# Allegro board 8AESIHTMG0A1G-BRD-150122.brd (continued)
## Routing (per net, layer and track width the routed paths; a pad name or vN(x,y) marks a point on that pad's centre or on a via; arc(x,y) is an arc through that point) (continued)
VCC3P3: length 210.4
  TOP w0.305: 48.98,67.35 C53.1 48.96,68.05 R57.1 ; 48.98,67.35 v4(49.73,66.6) ; 48.98,67.35 48.98,67.14 v4(48.56,66.73) ; v1(42.29,93.22) 42.19,93.22 42.12,93.15 U4.7
  TOP w0.356: v1(36.69,92.79) 36.66,92.82 U8.1
  TOP w0.635: U9.2 v3(47.47,87.66) ; U5.2 v3(29.18,91.89)
  TOP w0.762: 27.79,89.84 27.79,89.05 v4(27.64,88.9) ; 27.79,89.84 27.23,89.28 v4(26.54,89.28) ; 27.79,89.84 U5.1 ; 46.28,89.93 U9.1 ; 46.28,89.93 46.4,89.93 47.13,90.65 v4(47.14,90.65) ; 46.28,89.93 46.28,90.2 v4(45.87,90.61)
  L3_VCC w0.508: 34.37,169.7 34.37,170.18 v6(34.34,170.21)
  L3_VCC w1.524: v3(32.82,170.1) 33.96,170.1 38.5,165.57 41.39,165.57 42.41,164.55 ; 42.41,164.55 41.95,164.55 v4(41.31,163.92) ; 42.41,164.55 v4(43.07,163.89)
  BOTTOM w0.203: v1(47.42,66.65) 55.85,58.22 55.85,7.29 53.81,5.25 51.67,5.25 P2.24
  BOTTOM w0.305: v1(39.59,90.96) 39.61,90.98 R83.2 ; R82.2 42.27,91.76 v1(42.08,91.57) ; C82.1 42.12,93.15 42.19,93.22 v1(42.29,93.22)
  BOTTOM w0.356: v1(36.69,92.79) C84.1
  BOTTOM w0.508: J10.A21 33.4,169.52 v3(32.82,170.1) ; C87.1 29.21,91.87 v3(29.18,91.89) ; v6(34.34,170.21) 34.34,170.17 34.2,170.04 J10.A22 ; C89.1 47.34,87.53 v3(47.47,87.66)
  BOTTOM w0.635: v4(47.14,90.65) 47.1,90.61 46.97,90.61 46.57,90.22 46.57,90.06 ; 27.56,89.5 C85.1 ; 27.56,89.5 27.39,89.33 26.62,89.33 26.57,89.28 v4(26.54,89.28) ; 27.56,89.5 27.56,88.92 27.58,88.9 v4(27.64,88.9) ; 46.57,90.06 C88.1 ; 46.57,90.06 46.02,90.61 v4(45.87,90.61)
  BOTTOM w1.524: v4(51.08,82.3) 52.86,82.3 ; 52.86,82.3 v4(50.81,80.26) ; 52.86,82.3 55.22,84.66 55.22,105.36 52.3,108.28 52.3,111.66 54.69,114.05 54.69,148.93 43.07,160.55 43.07,162.67 ; 43.07,162.67 v4(43.07,163.89) ; 43.07,162.67 41.82,163.92 v4(41.31,163.92)
VDD1P2: length 30.4
  TOP w0.254: U10.47 38.22,83.54 v3(38.02,83.74) ; U10.43 38.17,81.54 v3(37.9,81.81) ; v3(37.85,79.15) 37.95,79.15 38.35,79.54 U10.39 ; v3(31.83,85.89) 31.83,85.72 31.88,85.67 U10.62 ; v3(30.35,86.09) 30.88,85.55 U10.64
  TOP w0.356: v1(26.82,78.87) 27.06,78.63 N4.2 ; N3.2 v1(26.92,85.12)
  TOP w0.508: R8.1 33.08,92.89 30.95,92.89 30.45,92.38 30.45,90.55 U5.3
  TOP w0.762: v3(30.2,88.85) 30.45,89.1 30.45,89.63 ; v4(31.22,89.05) 31.03,89.05 30.45,89.63 ; 30.45,89.63 U5.3
  BOTTOM w0.305: C91.1 40.29,84 v3(40.41,83.88) ; C97.1 30.81,83.78 31.2,83.39 v3(31.24,83.39) ; C102.1 30.82,81.4 31.13,81.71 v3(31.14,81.71)
  BOTTOM w0.356: v3(37.85,79.15) 37.92,79.15 38.42,79.64 C104.1 ; C94.1 32.25,85.47 v3(31.83,85.89) ; C96.1 38.19,83.58 v3(38.02,83.74) ; C95.1 30.59,85.84 v3(30.35,86.09) ; v3(37.9,81.81) 38.16,81.55 C101.1
  BOTTOM w0.508: v3(28.75,86.84) 28.38,86.46 C90.1
  BOTTOM w0.635: v3(30.2,88.85) 30.27,88.85 30.5,89.07 30.5,89.58 ; 30.5,89.58 C86.1 ; 30.5,89.58 31.03,89.05 v4(31.22,89.05)
VDD2P5: length 54.1
  TOP w0.254: v1(45.44,93.7) 45.39,93.65 U4.3 ; U10.37 39.96,78.54 v3(40.43,78.07) ; v3(35.23,86) 35.22,86 34.88,85.67 U10.56
  TOP w0.305: C56.1 28.1,63.75 v1(28.35,63.99) ; v1(29.82,63.14) 29.84,63.14 29.88,63.11 C57.2 ; C21.2 v1(50.87,90.68) ; C55.2 v1(51.77,65.04)
  TOP w0.356: T1.10 36.53,64.26 v1(36.2,64.59) ; T1.1 48.09,64.11 v1(47.57,64.62) ; R7.2 38.53,93.64 v1(38.48,93.6) ; v1(31.67,87.3) 31.68,87.29 R20.2 ; v1(38.86,92.84) 38.84,92.82 U8.6 ; R23.1 45.13,84.81 v1(45.16,84.84) ; v1(47.17,93.45) 47.15,93.43 R6.1 ; v1(44.12,64.54) 44.12,63.09 T1.4 ; R5.1 v1(38.5,94.66) ; R13.1 v1(38.23,89.13) ; R17.1 v1(42.32,89.05) ; v1(44.27,81.33) 44.2,81.4 R31.1 ; T1.7 v1(40.34,64.57) ; R10.1 v1(32.85,88.87) ; R36.1 43.28,78.19 v1(43.59,77.88) ; R16.1 v1(41.27,89.05) ; R11.2 v1(35.18,89)
  TOP w0.508: R29.1 45.09,81.8 v3(45.07,81.82)
  TOP w0.762: 44.8,86.39 44.8,86.03 v3(44.4,85.64) ; 44.8,86.39 v3(44.8,86.54) ; 44.8,86.39 U9.3
  BOTTOM w0.305: C80.1 21.7,93.6 v1(22.09,93.21) ; v1(22.83,77.75) 22.29,77.2 C107.1 ; v1(45.44,93.7) 45.37,93.77 C81.1 ; C76.2 v1(26.72,96.12) ; C75.2 v1(51.96,95.68)
  BOTTOM w0.356: 25.7,84.17 25.76,84.11 C98.1 ; v3(40.43,78.07) 40.03,78.47 C106.1 ; v1(36.2,64.59) 36.53,64.26 C128.1 ; C83.1 38.82,92.8 v1(38.86,92.84) ; 26.54,74.5 26.56,74.51 C120.1 ; C126.1 v1(44.12,64.54) ; C93.1 34.81,85.6 35.22,86 v3(35.23,86) ; C117.1 44.42,75.01 44.47,74.96 ; v1(47.57,64.62) 48.08,64.11 C129.1 ; C127.1 40.34,63.77 v1(40.34,64.57)
  BOTTOM w0.508: 26.54,74.02 25.82,73.3 v4(25.68,73.3) ; 26.54,74.02 26.54,73.54 26.54,72.62 v4(26.54,72.62) ; 26.54,74.02 L8.1 ; v4(44.97,73.65) 44.97,73.76 44.47,74.25 ; 45.12,86.21 C92.1 ; 45.12,86.21 44.98,86.21 v3(44.4,85.64) ; 45.12,86.21 v3(44.8,86.54) ; v4(43.86,73.68) 43.9,73.68 44.47,74.25 ; 25.7,84.17 24.77,84.17 v4(24.77,84.17) ; 25.7,84.17 25.7,84.92 v4(25.6,85.02) ; 25.7,84.17 L7.1 ; 44.47,74.25 44.47,74.96 43.25,74.96 L9.1
VDD5P0SB: length 20.5
  TOP w0.762: F1.2 9.88,170.79 10.58,170.1 v7(10.62,170.1)
  BOTTOM w0.254: 10.52,170.07 R81.1
  BOTTOM w0.635: J10.A5 20.6,166.52 20.19,166.1 19.79,166.1 19.8,166.11 J10.A4
  BOTTOM w0.762: v7(10.62,170.1) 10.55,170.1 10.52,170.07 10.52,166.43 11.42,165.53 15.24,165.53 15.81,166.1 19.79,166.1
VDD12P0: length 81.4
  TOP w0.305: 25.21,99.23 C17.1 25.73,99.72
  TOP w0.508: U2.3 27.38,101.6 ; U2.3 27.38,100.23 ; U2.3 28.32,100.91 ; U2.3 26.44,100.91 ; 25.77,101.02 C16.1 25.34,100.37
  TOP w0.762: v4(22.63,143.7) 19.81,146.52 19.81,168.59 20.88,169.66 v7(20.88,169.96)
  BOTTOM w0.635: J10.A6 21.4,169.43 20.88,169.94 v7(20.88,169.96)
  BOTTOM w0.762: v4(25.82,99.1) 25.82,112.48 22.63,115.66 v4(22.63,143.7)
1PPS_OUT_CLK: length 174.1
  TOP w0.203: P4.1 7,12.08 8.35,13.43 D4.1 9.09,14.4 9.74,15.05 9.74,19.19 2.08,26.85 2.08,95.19 12.48,105.59 v1(12.48,167.12)
  BOTTOM w0.203: J10.A1 15.3,167.89 14.48,167.08 12.52,167.08 v1(12.48,167.12)
88E1112_25M_REFCLK: length 102.4
  TOP w0.203: v1(44.45,78.99) 44.46,78.98 R38.2 44.46,78.1 R39.1
  BOTTOM w0.203: v1(44.45,78.99) 44.45,79.69 49.65,84.89 49.65,97.48 53.27,101.09 53.27,103.92 50.29,106.9 50.29,112.51 51.94,114.16 51.94,148.87 37.4,163.42 J10.A26
88E1112_INT_L: length 102.2
  TOP w0.203: U8.3 36.39,91.37 v1(36.7,91.06) ; v1(35.26,157.02) 37.4,159.17 v1(37.4,170.78)
  BOTTOM w0.203: J10.B26 v1(37.4,170.78) ; v1(35.26,157.02) 34.67,157.02 28.06,150.41 25.53,150.41 20.29,145.17 20.29,100.51 26.6,94.19 31.79,94.19 34.92,91.06 v1(36.7,91.06)
88E1112_RST_L: length 102.6
  TOP w0.203: C22.1 36.19,87.64 36.19,86.54 v1(36.45,86.28) 36.88,85.85 U10.52
  BOTTOM w0.203: J10.A24 35.8,158.89 27.74,150.83 25.31,150.83 19.87,145.39 19.87,100.33 26.44,93.76 31.47,93.76 34.46,90.76 34.46,88.86 36.45,86.87 v1(36.45,86.28)
5221_50M_RMII_REFCLK: length 106.4
  TOP w0.203: v1(23.65,165.07) 23.65,164.54 v5(21.99,162.88) ; v1(8.15,74.9) 8.34,74.72 9.4,74.72 9.57,74.89 U11.4
  BOTTOM w0.203: v1(8.15,74.9) 8.15,77.22 11.53,80.59 11.53,155.77 18.48,162.73 21.84,162.73 v5(21.99,162.88) ; J10.A13 27,166.45 25.62,165.07 v1(23.65,165.07)
5221_ACTLED: length 5.7
  TOP w0.203: U12.2 24.15,66.17 24.03,66.3 R62.2 R61.1 22.42,66.58 22.07,66.93 v1(22.07,67.56) U11.33
5221_AVDD: length 11.3
  TOP w0.254: v3(14.71,65.56) 15.01,65.86 U11.22 ; v3(17.5,65.51) 17.51,65.51 U11.27 ; v3(18.41,65.52) 18.41,65.53 18.01,65.94 U11.28
  BOTTOM w0.356: v3(17.5,65.51) 17.5,65.62 17.28,65.84 C122.1 ; C124.1 18.3,65.65 18.33,65.61 ; C123.1 15.07,65.92 v3(14.71,65.56)
  BOTTOM w0.508: v3(14.71,65.56) 17.45,65.56 v3(17.5,65.51) 17.61,65.61 18.33,65.61 18.41,65.53 v3(18.41,65.52)
5221_INT_L: length 111.6
  TOP w0.203: v1(25.98,153.09) 26.37,153.47 26.37,170.84 v1(26.2,171.01) ; v1(23.39,68.76) 23.39,68.97 22.97,69.39 U11.34
  BOTTOM w0.203: J10.B12 v1(26.2,171.01) ; v1(23.39,68.76) 23.39,73.17 24.37,74.15 24.37,80.53 22.95,81.96 22.95,88.96 23.49,89.5 23.49,95.54 19.03,100 19.03,145.86 25.96,152.78 25.96,153.06 v1(25.98,153.09)
5221_LNKACT: length 29.4
  TOP w0.203: v1(26.46,65.43) 26.49,65.45 U12.4 ; v1(24.18,88.78) 22.97,88.78 22.76,88.98 U6.5
  BOTTOM w0.203: v1(26.46,65.43) 25.81,66.08 25.81,68.26 24.39,69.68 24.39,72.94 25.49,74.03 25.49,80.78 23.84,82.42 23.84,88.44 v1(24.18,88.78)
5221_LNKACT_B: length 102.6
  TOP w0.203: U6.10 22.76,97.33 23.33,97.9 33.58,97.9 v2(34.19,97.29) 34.83,96.65 52.81,96.65 55.88,93.57 55.88,33.07 52.37,29.57 R78.1
5221_LNKACT_C: length 86.7
  TOP w0.203: v1(34.09,165.4) 34.78,164.71 34.78,159.86 29.78,154.86 v1(29.78,154.28) ; U6.8 25.43,95.09 v1(24.83,94.49)
  BOTTOM w0.203: J10.A19 31.8,166.5 32.9,165.4 v1(34.09,165.4) ; v1(24.83,94.49) 24.83,94.78 19.44,100.17 19.44,145.61 25.1,151.27 26.77,151.27 v1(29.78,154.28)
5221_RD_N: length 14.7
  TOP w0.152: 16.42,64.52 16.58,64.68 16.58,65.82 16.51,65.89 U11.25 ; 16.42,64.52 R65.1 ; 16.42,64.52 16.58,64.36 16.58,62.42 18.82,60.17 21.85,60.17 22.02,60.01 22.02,59.61 21.84,59.44 21.21,59.44 20.76,58.99 T2.8
5221_RD_P: length 14.4
  TOP w0.152: 17.02,64.5 16.93,64.41 16.93,62.56 18.97,60.53 22,60.53 22.37,60.15 22.37,59.54 22.48,59.44 22.86,59.44 23.43,58.87 T2.6 ; 17.02,64.5 R68.1 ; 17.02,64.5 16.93,64.59 16.93,65.82 17.01,65.89 U11.26
5221_RST_L: length 113.6
  TOP w0.203: v1(12.62,72.75) 12.27,72.39 U11.9 ; v1(22.71,166.28) 22.28,165.85 22.28,164.8 v1(21.82,164.34)
  BOTTOM w0.203: J10.A11 25.4,166.51 25.17,166.28 v1(22.71,166.28) ; v1(21.82,164.34) 21.81,164.34 21.32,163.84 17.91,163.84 10.43,156.37 10.43,81.67 7.24,78.48 7.24,73.59 7.95,72.87 8.6,72.87 9.06,72.42 12.29,72.42 v1(12.62,72.75)
5221_SPDLED: length 68
  TOP w0.203: v1(35.89,27.25) 35.96,27.18 R79.1 ; R55.2 25.37,70.38 25.73,70.03 25.73,67.2 U12.1 v1(24.52,66.9) 24.17,67.24 R59.2
  BOTTOM w0.203: v1(35.89,27.25) 34.7,28.44 32.37,28.44 30.76,30.05 30.76,35.89 24.64,42.01 18.86,42.01 14.5,46.36 14.5,58.32 18.08,61.9 23.37,61.9 25.02,63.55 25.02,66.4 v1(24.52,66.9)
5221_TD_N: length 18.6
  TOP w0.152: 19.18,64.51 19.3,64.64 19.3,65.02 19.08,65.25 19.08,65.82 19.01,65.89 U11.30 ; 19.18,64.51 19.3,64.39 19.3,62.64 20.09,61.85 27.33,61.85 28.32,60.86 28.32,59.56 28.19,59.44 27.69,59.44 27.24,58.99 T2.3 ; 19.18,64.51 R67.1
5221_TD_P: length 18.6
  TOP w0.152: 19.77,64.52 19.66,64.63 19.66,65.17 19.43,65.4 19.43,65.82 19.51,65.89 U11.31 ; 19.77,64.52 19.66,64.41 19.66,62.78 20.24,62.2 27.48,62.2 28.68,61.01 28.68,59.61 28.83,59.46 29.31,59.46 29.91,58.87 T2.1 ; 19.77,64.52 R66.1
ANEN_5221: length 3.7
  TOP w0.203: v1(20.5,71.48) 20.58,71.39 U11.38 24.16,71.39 R54.1
BIAS3V3: length 61.1
  TOP w0.254: U11.8 11.54,72.89 v3(11.7,73.05) ; U11.46 20.85,75.39 v3(20.62,75.62) ; v3(11.66,76.66) 11.5,76.5 U11.1 ; U11.20 14.01,65.9 13.74,65.63 v3(13.59,65.63) ; U11.3 v3(11.69,75.39)
  TOP w0.305: 50.29,26.44 50.24,26.44 49.91,26.11 v3(49.91,25.76) ; 50.29,26.44 49.91,26.82 v3(49.91,27.03) ; 50.29,26.44 C74.1 ; C56.2 v1(26.15,63.75) ; C24.2 v1(6.21,83.54) ; v1(23.57,161.71) 23.29,161.43 C4.2 ; C58.2 v1(7.02,61.33) ; C1.2 v1(10.24,174.82) ; C72.2 v1(12.69,26.98) ; C6.2 v1(6.15,147.15) ; C12.2 v1(6.82,113.01)
  TOP w0.356: R56.1 v1(24.85,68.49) ; R70.2 v1(9.27,59.56) ; P2.20 50.32,24.69 50.78,25.16 C74.1 ; R54.2 v1(25.55,71.4) ; U13.26 7.62,54.73 v1(7.37,54.48) ; R71.2 v1(10.29,59.56) ; R62.1 v1(23.46,64.84) ; R59.1 v1(22.83,68.07) ; R45.2 v1(24.9,72.16)
  TOP w0.381: J9.1 5.64,69.21 4.88,68.45 v1(4.62,68.45) ; J6.1 4.98,72.31 v1(4.6,72.69) ; J5.1 5.69,73.41 4.72,74.37 v1(4.6,74.37) ; J7.1 4.92,71.28 v1(4.6,71.6) ; v1(4.6,70.56) 4.92,70.24 J8.1
  TOP w0.508: v1(26.54,66.93) 26.58,66.9 U12.5 ; J4.3 9.17,88.37 v1(8.64,88.9) ; v1(6.6,94.36) 6.55,94.41 U7.8 ; U6.14 17.55,97.81 v1(17.42,97.94) ; v1(7.77,88.09) 7.9,87.96 J3.3 ; v1(16.1,57.91) 16.1,58.13 L2.1 ; J2.3 v1(6.38,88.09)
  L3_VCC w0.508: 38.2,23.36 P2.18 ; P2.18 39.14,24.3 ; P2.18 40.08,23.36 ; P2.18 39.14,22.42
  BOTTOM w0.305: C107.2 20.57,77.2 v1(20.35,76.98) ; C80.2 v1(20.24,94.01)
  BOTTOM w0.356: C108.2 11.62,76.62 v3(11.66,76.66) ; C79.1 C77.1 17.67,97.7 v1(17.42,97.94) ; v1(6.6,94.36) 6.87,94.63 C78.2 ; v3(11.69,75.39) 11.65,75.43 C118.2 ; v3(20.62,75.62) 20.74,75.5 C119.2 ; v1(7.37,54.48) 7.51,54.62 C132.2 ; C121.2 11.58,72.94 v3(11.7,73.05) ; C125.2 13.95,65.99 v3(13.59,65.63)
  BOTTOM w0.508: J10.B22 34.2,173.9 v3(34.39,174.09) ; v6(33.28,174.22) 33.4,174.1 J10.B21
C1P: length 2.4
  TOP w0.203: C60.2 5.84,57.35 v1(5.79,57.3) 6.19,56.9 U13.28
C2N: length 2.2
  TOP w0.203: U13.2 6.97,47.38 6.81,47.22 v1(6.81,47.22) 6.81,47.07 6.85,47.03 C64.1
C2P: length 2.9
  TOP w0.203: U13.1 6.19,47.12 6.11,47.04 C64.2 v1(5.44,46.35)
CLK_25M_MNGPHY: length 6.2
  TOP w0.203: R39.2 43.71,77.08 R41.2 42.52,77.23 R42.1 40.5,77.23 39.69,78.04 U10.36 38.19,78.04 v1(37.97,78.26)
CLK_25M_OCXO: length 50.4
  TOP w0.203: J1.2 25.43,129.9 24.92,130.4 24.92,164.37 25.19,164.65 25.19,170.36 v5(24.6,170.95)
  BOTTOM w0.203: J10.B10 v5(24.6,170.95)
CPU_PHY_SGMII_N: length 143.5
  TOP w0.152: v1(43.81,176.68) 43.48,176.35 43.48,175.7 43.12,175.34 42.41,175.34 41.84,175.92 24.85,175.92 21.86,172.93 17.27,172.93 16.36,172.01 16.36,101.32 13.11,98.07 13.11,88.23 15.79,85.55 20.7,85.55 25.81,80.44 26.27,80.44 26.6,80.77 C28.1
  BOTTOM w0.152: J10.A30 40.6,169.07 40.42,169.25 40.42,169.47 40.63,169.68 40.89,169.68 41.05,169.84 41.05,170 41.05,170.1 41.2,170.25 41.46,170.25 41.62,170.41 41.62,170.58 41.62,170.67 41.78,170.83 42.04,170.83 42.2,170.99 42.2,171.15 42.2,171.25 42.35,171.4 42.61,171.4 42.77,171.56 42.77,171.73 42.77,171.82 43.48,172.54 43.48,176.35 v1(43.81,176.68)
CPU_PHY_SGMII_P: length 143.5
  TOP w0.152: C29.1 26.6,79.76 26.27,80.09 25.66,80.09 20.55,85.19 15.64,85.19 12.75,88.09 12.75,98.22 16,101.47 16,172.16 17.12,173.28 21.72,173.28 24.71,176.27 41.98,176.27 42.56,175.7 42.98,175.7 43.13,175.85 43.13,176.35 v1(42.8,176.68)
  BOTTOM w0.152: J10.A29 39.8,169.07 40.06,169.33 40.06,169.62 43.13,172.68 43.13,176.35 v1(42.8,176.68)
FORCEOFF: length 2.5
  TOP w0.203: R71.1 10.29,57.63 v1(10.62,57.3) 10.22,56.9 U13.22
FORCEON: length 2.3
  TOP w0.203: U13.23 9.57,57.11 v1(9.35,57.33) 9.27,57.4 R70.1
I2C_SCL_MG: length 95.2
  TOP w0.203: U7.6 9.22,96.88 v1(8.69,97.41)
  BOTTOM w0.203: J10.A23 35,164.74 34.21,163.95 23.5,163.95 21.79,165.67 20.63,165.67 20.16,165.2 17.49,165.2 9.16,156.87 9.16,97.88 v1(8.69,97.41)
I2C_SDA_MG: length 104.6
  TOP w0.203: U7.5 10.62,97.99 v2(11.15,98.53) 14.69,102.06 14.69,168.78 13.75,169.71 13.75,172.02 16.08,174.35 20.32,174.35 23.59,177.62 v1(32.52,177.62)
  BOTTOM w0.203: v1(32.52,177.62) 32.6,177.54 J10.B20
LED_ACT_MGMT1: length 4.9
  TOP w0.203: P2.19 52.86,27.28 52.37,27.76 R78.2
LED_ACT_MGMT_R: length 24.9
  TOP w0.203: R77.2 51.84,24.71 51.59,24.46 51.59,23.14 52.73,22 54.03,22 55.85,20.17 55.85,7.62 54.84,6.6 P2.23
LED_SPD_MGMT1_R: length 9.1
  TOP w0.203: P2.17 40.41,22.1 37.24,22.1 35.96,23.37 R79.2
LED_STUS0_MGMT: length 60
  TOP w0.203: v1(42.62,77.93) 42.43,78.12 R37.2 41.19,78.12 40.87,78.44 40.87,79.02 39.84,80.04 U10.40 ; U6.1 17.55,91.95 18.24,92.63 25.44,92.63 26.93,94.12 35.27,94.12 36.95,95.81 46.47,95.81 47.84,94.43 47.84,93.18 45.96,91.31 44.39,91.31 43.92,90.83 43.92,86.42 43.41,85.91 R21.2 42.77,85.27 v1(42.75,85.24) 42.77,85.22 R25.2
  BOTTOM w0.203: v1(42.62,77.93) 41.91,78.64 41.91,84.4 v1(42.75,85.24)
LED_STUS0_MGMT_B: length 106.5
  TOP w0.203: R77.1 51.84,30.15 55.4,33.71 55.4,93.27 52.44,96.23 35.73,96.23 v2(35.31,95.8) 34.23,94.73 26.69,94.73 25.9,93.93 21.11,93.93 20.22,94.82 U6.12
LED_STUS0_MGMT_C: length 94.6
  TOP w0.203: v1(32.69,156.93) 35.26,159.5 35.26,165.29 v1(34.41,166.14) ; U6.4 21.49,91.71 21.12,92.08 v1(19.63,92.08)
  BOTTOM w0.203: v1(34.41,166.14) 33.17,166.14 32.6,166.71 J10.A20 ; v1(19.63,92.08) 19.66,92.08 19.67,92.08 19.67,97.4 17.8,99.27 17.8,151.49 21.47,155.15 30.91,155.15 v1(32.69,156.93)
LED_STUS1_MGMT: length 129.9
  TOP w0.203: R24.2 41.74,84.61 v1(41.74,85.32) R22.2 ; v1(32.07,29.54) 32.91,28.7 33.4,28.7 34.06,28.04 34.06,23.19 35.75,21.5 35.75,7.02 37.59,5.18 40.13,5.18 41.55,6.6 P2.21 ; v1(40.92,81.31) 40.92,81.1 41.31,80.71 R34.2 ; U10.38 39.95,79.04 40.01,79.1 v1(40.06,79.1) ; v1(41.08,83.02) 41.82,83.02 R28.2
  BOTTOM w0.203: v1(41.74,85.32) 41.08,84.66 v1(41.08,83.02) 40.87,82.81 40.87,81.36 v1(40.92,81.31) 40.04,80.43 40.04,79.11 ; v1(32.07,29.54) 32.07,29.55 31.55,30.07 31.55,35.81 24.92,42.44 19.13,42.44 14.94,46.64 14.94,58.12 18.21,61.39 26.67,61.39 37.47,72.19 45.06,72.19 46.13,73.25 46.13,76.63 45.43,77.32 41.98,77.32 40.19,79.11 40.04,79.11 ; 40.04,79.11 v1(40.06,79.1)
LP_5221: length 4.2
  TOP w0.203: R60.2 8.91,67.03 v2(9.04,66.9) 9.37,66.9 10.44,67.97 U11.16
MCT: length 15
  TOP w0.508: v4(49.38,48.46) 49.81,48.03 C63.1
  BOTTOM w0.508: R89.2 R88.2 R87.2 R86.2 49.36,48.48 v4(49.38,48.46)
MCT1: length 2.5
  TOP w0.356: T1.24 48.09,46.18 v3(48.08,46.17)
  BOTTOM w0.508: R86.1 48.08,46.18 v3(48.08,46.17)
MCT2: length 2.5
  TOP w0.356: v3(44.13,46.17) 44.13,46.21 44.15,46.22 T1.21
  BOTTOM w0.508: v3(44.13,46.17) 44.13,46.21 44.15,46.22 R87.1
MCT3: length 2.5
  TOP w0.356: T1.18 40.34,46.26 40.33,46.25 v3(40.33,46.19)
  BOTTOM w0.508: R88.1 40.34,46.19 v3(40.33,46.19)
MCT4: length 2.7
  TOP w0.356: v3(36.69,46.15) 36.69,46.24 36.53,46.4 T1.15
  BOTTOM w0.508: R89.1 36.53,46.41 36.69,46.24 v3(36.69,46.15)
MDC_88E1112: length 110.9
  TOP w0.203: v1(35,170.92) 35.69,170.23 35.69,159.32 33.32,156.96 v1(33.32,153.99) ; U4.1 44.56,91.83 v1(44.54,91.81)
  BOTTOM w0.203: v1(33.32,153.99) 28.9,149.57 25.88,149.57 21.1,144.79 21.1,115.04 24.38,111.76 24.38,109.24 21.18,106.04 21.18,100.81 26.81,95.19 41.2,95.19 43.67,92.71 R82.1 44.49,91.76 v1(44.54,91.81) ; J10.B23 35,170.92 v1(35,170.92)
MDC_5221: length 110.4
  TOP w0.203: U11.42 22.9,73.39 v1(23.39,73.88) ; v1(27.05,153.85) 26.8,154.1 26.8,170.66 27,170.87 v1(27,170.99)
  BOTTOM w0.203: J10.B13 v1(27,170.99) ; v1(27.05,153.85) 27.03,153.85 26.6,154.27 21.75,154.27 18.63,151.15 18.63,99.76 23.06,95.32 23.06,89.7 22.53,89.16 22.53,81.79 23.92,80.39 23.92,74.42 v1(23.39,73.88)
MDIO_88E1112: length 106.2
  TOP w0.203: U4.8 41.39,91.78 v1(41.28,91.68) ; v1(34.49,155.27) 34.49,157.49 36.09,159.09 36.09,170.59 v1(35.8,170.88)
  BOTTOM w0.203: J10.B24 v1(35.8,170.88) ; v1(34.49,155.27) 33.68,155.27 28.4,149.99 25.71,149.99 20.7,144.98 20.7,100.69 26.75,94.64 35.54,94.64 36.07,94.11 39.06,94.11 40.34,92.83 R83.1 41.23,91.73 v1(41.28,91.68)
MDIO_5221: length 115.4
  TOP w0.203: U11.41 24.16,72.89 R45.1 24.17,73.37 26.26,75.46 26.26,77.52 22.76,81.03 v1(22.54,81.03) ; v1(28.19,154.51) 27.2,155.5 27.2,170.36 v1(27.8,170.95)
  BOTTOM w0.203: v1(28.19,154.51) 27.97,154.73 21.62,154.73 18.22,151.33 18.22,99.56 22.64,95.14 22.64,89.93 22.06,89.34 22.06,81.51 v1(22.54,81.03) ; J10.B14 v1(27.8,170.95)
MGMT_INT#_2P5: length 12.6
  TOP w0.203: U8.4 37.8,90.76 37.52,90.48 33.93,90.48 v2(33.65,90.2) 33.4,90.2 31.18,87.98 31.18,86.87 31.51,86.55 R20.1 32.38,86.54 U10.61
MGT_TRD1_0_N: length 19.4
  TOP w0.152: C38.1 R47.2 29.6,72.25 ; U10.19 31.88,75.06 31.81,74.99 31.81,74.39 30.35,72.92 29.72,72.92 29.57,72.77 29.57,72.29 29.6,72.25 ; 29.6,72.25 29.6,72.2 29.57,72.16 29.57,67.97 31.54,65.99 33.88,65.99 34.8,65.07 34.8,64.69 35.26,64.23 T1.11
MGT_TRD1_0_P: length 19.4
  TOP w0.152: 29.12,72.25 29.21,72.34 29.21,72.92 29.57,73.28 30.2,73.28 31.46,74.53 31.46,74.99 31.38,75.06 U10.18 ; 29.12,72.25 R46.1 C37.1 ; 29.12,72.25 29.21,72.16 29.21,67.82 31.39,65.63 33.74,65.63 34.44,64.93 34.44,64.77 33.86,64.19 T1.12
MGT_TRD1_0_TERM: length 4
  TOP w0.203: R46.2 v1(28.7,70.87) C45.1 ; C46.1 v1(30.1,70.87) R47.1
  BOTTOM w0.203: v1(30.1,70.87) v1(28.7,70.87)
MGT_TRD1_1_N: length 17.6
  TOP w0.152: 34.12,72.25 R49.2 C40.1 ; 34.12,72.25 34.04,72.34 34.04,73.64 33.31,74.36 33.31,74.99 33.38,75.06 U10.22 ; 34.12,72.25 34.04,72.16 34.04,68.35 36.22,66.17 37.87,66.17 38.61,65.43 38.61,64.67 39.07,64.21 T1.8
MGT_TRD1_1_P: length 17.7
  TOP w0.152: 33.62,72.25 R48.1 C39.1 ; 33.62,72.25 33.68,72.31 33.68,73.49 32.96,74.21 32.96,74.99 32.88,75.06 U10.21 ; 33.62,72.25 33.68,72.19 33.68,68.2 36.07,65.81 37.72,65.81 38.25,65.28 38.25,64.67 37.8,64.21 T1.9
MGT_TRD1_1_TERM: length 4
  TOP w0.203: C47.1 33.15,70.82 v1(33.17,70.84) 33.15,70.87 R48.2 ; R49.1 34.54,70.87 v1(34.57,70.84) 34.54,70.82 C48.1
  BOTTOM w0.203: v1(34.57,70.84) v1(33.17,70.84)
MGT_TRD1_2_N: length 18.5
  TOP w0.152: 38.57,72.22 38.48,72.31 38.48,72.99 38.09,73.38 36.98,73.38 36.31,74.05 36.31,74.99 36.38,75.06 U10.28 ; 38.57,72.22 38.48,72.14 38.48,68.19 40.23,66.45 41.65,66.45 42.42,65.68 42.42,64.77 42.88,64.31 T1.5 ; 38.57,72.22 38.57,72.25 R51.2 C42.1
MGT_TRD1_2_P: length 18.5
  TOP w0.152: 38.01,72.25 38.13,72.36 38.13,72.85 37.95,73.03 36.84,73.03 35.96,73.9 35.96,74.99 35.88,75.06 U10.27 ; 38.01,72.25 R50.1 C41.1 ; 38.01,72.25 38.13,72.14 38.13,68.05 40.08,66.09 41.5,66.09 42.06,65.53 42.06,64.8 41.61,64.34 T1.6
MGT_TRD1_2_TERM: length 4
  TOP w0.203: C50.1 v1(38.99,70.84) R51.1 ; C49.1 v1(37.59,70.82) R50.2
  BOTTOM w0.203: v1(38.99,70.84) 37.62,70.84 v1(37.59,70.82)
MGT_TRD1_3_N: length 19.9
  TOP w0.152: C44.1 R53.2 43.07,72.25 ; 43.07,72.25 42.93,72.39 42.93,73.05 42.57,73.41 39.93,73.41 38.82,74.52 38.07,74.52 37.81,74.78 37.81,74.99 37.88,75.06 U10.31 ; 43.07,72.25 42.93,72.11 42.93,68.43 46.23,65.13 46.23,64.72 46.69,64.26 T1.2
MGT_TRD1_3_P: length 20
  TOP w0.152: 42.46,72.25 42.57,72.14 42.57,68.28 45.87,64.98 45.87,64.74 45.42,64.29 T1.3 ; 42.46,72.25 42.57,72.36 42.57,72.9 42.42,73.05 39.79,73.05 38.67,74.17 37.92,74.17 37.46,74.63 37.46,74.99 37.38,75.06 U10.30 ; 42.46,72.25 R52.1 C43.1
MGT_TRD1_3_TERM: length 4
  TOP w0.203: R52.2 42.04,70.87 v1(42.01,70.84) 42.04,70.82 C51.1 ; R53.1 v1(43.43,70.84) C52.1
  BOTTOM w0.203: v1(43.43,70.84) v1(42.01,70.84)
MII_EN_5221: length 3.2
  TOP w0.203: U11.18 13.01,65.35 13.11,65.25 R63.2 v1(13.98,64.55)
MNG_PHY_CFG0: length 7.9
  TOP w0.203: R17.2 R18.2 43.36,86.79 43.21,86.64 R21.1 R22.1 41.31,86.64 v2(40.38,85.71) 40.38,84.64 39.78,84.04 U10.48
MNG_PHY_CFG1: length 7.2
  TOP w0.203: 41.16,83.85 40.36,83.04 U10.46 ; 41.16,83.85 41.17,83.86 R24.1 ; 41.16,83.85 41.84,83.85 41.85,83.86 42.77,83.86 R25.1 ; R25.1 v1(42.77,83.23) ; R25.1 43.65,83.85 R26.2 43.73,84.8 R23.2
MNG_PHY_CFG2: length 3.8
  TOP w0.203: R30.2 42.64,82.28 R28.1 41.24,82.28 40.98,82.54 v1(40.24,82.54) U10.45
MNG_PHY_CFG3: length 4.7
  TOP w0.203: U10.44 40.89,82.04 41.49,81.44 R34.1 42.72,81.44 R31.2 v1(42.77,80.62)
MNG_PHY_CFG4: length 4.5
  TOP w0.203: R35.2 41.55,79.78 40.29,81.04 U10.42 37.89,81.04 v1(37.77,80.92)
MNG_PHY_CFG5: length 4.2
  TOP w0.203: R36.2 42.43,78.85 R37.1 41.6,78.97 v1(40.59,79.98) 40.03,80.54 U10.41
MNG_PHY_LOS_L: length 95.6
  TOP w0.203: v1(32.16,88.19) 32.21,88.13 R10.2 33.57,88.11 R19.2 ; v1(34.87,27.25) 34.87,27.18 34.91,27.14 R80.1
  BOTTOM w0.203: v1(32.16,88.19) 31.96,87.99 26.92,87.99 25.59,89.32 23.99,89.32 23.4,88.74 23.4,82.12 24.97,80.55 24.97,74.15 23.95,73.13 23.95,64.14 22.23,62.41 17.87,62.41 14,58.53 14,46.15 18.59,41.55 24.38,41.55 30,35.94 30,29.72 32.65,27.07 34.69,27.07 v1(34.87,27.25)
MNG_PHY_LOS_R_L: length 1.9
  TOP w0.203: U10.59 v1(33.38,85.85) 33.38,86.02 33.57,86.21 R19.1
MNG_PHY_MDC_2P5: length 20.3
  TOP w0.203: R6.2 46.29,94.23 U4.4 43.68,94.23 43.25,93.79 43.25,91.18 42.9,90.84 v2(42.9,90.3) 42.14,90.3 41.48,89.63 34.95,89.63 34.64,89.33 34.64,86.12 34.38,85.86 U10.57
MNG_PHY_MDIO_2P5: length 20.2
  TOP w0.203: U10.58 33.88,85.94 34.21,86.27 34.21,89.48 34.79,90.06 41.3,90.06 41.53,90.28 v2(41.53,90.83) 42.29,90.83 42.29,90.83 42.8,91.33 42.8,93.85 42.42,94.23 U4.5 40.8,94.23 40.36,94.66 R5.2
MNG_PHY_NORMAL: length 4.7
  TOP w0.203: R16.2 R15.1 40.26,87.38 39.29,86.41 v2(39.14,86.41) 38.38,85.65 U10.49
MNG_PHY_POL_RST: length 3.1
  TOP w0.203: R12.1 37.21,87.33 v1(37.54,87) 37.38,86.84 U10.51
MNG_PHY_PWRDN: length 4.5
  TOP w0.203: U10.50 37.88,85.74 v1(37.87,85.75) 37.87,85.98 39.24,87.35 R14.1 R13.2
MNG_PHY_VDDA: length 15.3
  TOP w0.254: U10.33 40.19,76.54 v3(40.31,76.43) ; U10.23 v3(33.88,74.78) ; v3(32.41,74.31) 32.38,74.34 U10.20 ; U10.24 34.38,75.06 34.85,74.6 v3(34.85,74.37) ; U10.29 v3(36.88,74.68)
  BOTTOM w0.356: v3(40.31,76.43) 40.17,76.57 C111.1 ; v3(32.41,74.31) 32.25,74.48 C116.1 ; v3(33.88,74.78) 33.9,74.79 C115.1 ; v3(36.88,74.68) 36.97,74.76 C113.1 ; C114.1 34.81,74.41 v3(34.85,74.37)
  BOTTOM w0.508: v3(40.31,76.43) 40.35,76.47 C112.1 43.15,76.47 L9.2
MNG_PHY_VDDAH: length 11.2
  TOP w0.254: v3(29.1,76.75) 29.1,77.1 29.54,77.54 U10.14 ; v3(28.65,80.99) 28.7,80.99 28.75,81.04 U10.7
  BOTTOM w0.305: v3(28.65,80.99) 28.59,80.93 C103.1 28.18,80.26
  BOTTOM w0.356: v3(29.1,76.75) 29.17,76.82 C110.1
  BOTTOM w0.508: C109.1 28.18,77.45 28.18,80.26 ; C109.1 28.71,77.2 29.1,76.81 v3(29.1,76.75) ; C109.1 26.57,77.2 L8.2
MNG_PHY_VDDAL: length 11.4
  TOP w0.254: v3(29.03,77.93) 29.15,78.04 U10.13 ; U10.6 29.33,81.54 28.95,81.92 v3(28.92,81.92)
  BOTTOM w0.305: 28.31,82.67 28.24,82.74 C99.1
  BOTTOM w0.356: C100.1 30.01,81.8 29.9,81.69 ; 28.55,82.55 28.43,82.67 28.31,82.67
  BOTTOM w0.508: v3(29.03,77.93) 29.04,77.93 29.24,78.13 C105.1 30.04,81.55 29.87,81.71 29.16,81.71 28.95,81.92 v3(28.92,81.92) 28.85,81.99 28.85,82.25 28.55,82.55 27.01,82.55 L7.2
MNG_SFP_RSET: length 3.1
  TOP w0.203: R44.2 v1(29.79,74.3) 30.34,74.3 30.88,74.83 U10.17
MNG_SGMII_C_N: length 2.6
  TOP w0.152: U10.8 29.21,80.54 29.14,80.47 27.97,80.47 C28.2
MNG_SGMII_C_P: length 2.7
  TOP w0.152: C29.2 28.03,80.12 29.15,80.12 29.23,80.04 U10.9
MNGPHY_SDA: length 3.4
  TOP w0.203: R11.1 35.19,87.63 35.19,87.03 v1(35.15,87) 35.15,86.87 36.38,85.64 U10.53
MX0_A_0N: length 45.7
  TOP w0.152: v1(29.16,42.85) 29.54,43.23 29.54,44.78 28.32,46 28.32,46.43 28.17,46.58 27.57,46.58 27.24,46.91 T2.14
  BOTTOM w0.152: v1(29.16,42.85) 29.49,42.52 29.49,41.88 31.85,39.52 40.9,39.52 41.81,38.61 41.81,30.25 45.14,26.92 45.14,21.31 43.94,20.11 43.94,18.5 44.09,18.34 P2.6
MX0_A_0P: length 48.3
  TOP w0.152: T2.16 29.91,47.07 29.5,46.66 28.91,46.66 28.68,46.43 28.68,46.15 29.9,44.93 29.9,43.13 v1(30.18,42.85)
  BOTTOM w0.152: v1(30.18,42.85) 29.84,42.52 29.84,42.03 32,39.88 41.05,39.88 42.16,38.76 42.16,30.4 45.49,27.07 45.49,21.16 44.3,19.96 44.3,18.64 44.81,18.14 46.61,18.14 P2.3
MX0_A_1N: length 59.6
  TOP w0.152: T2.9 20.76,47.11 21.18,46.69 21.79,46.69 21.97,46.51 21.97,45.16 v1(21.64,44.83)
  BOTTOM w0.152: v1(21.64,44.83) 21.97,45.16 21.97,45.87 22.45,46.35 25.65,46.35 26.64,45.36 34.59,45.36 35.71,44.25 41.3,44.25 44.75,40.79 44.75,32.46 47.73,29.49 47.73,22.6 49.49,20.84 50.48,20.84 51.46,19.85 51.46,19 50.52,18.06 50.34,18.06 P2.2
MX0_A_1P: length 54.4
  TOP w0.152: T2.11 23.43,47.2 22.94,46.71 22.56,46.71 22.33,46.48 22.33,45.16 v1(22.66,44.83)
  BOTTOM w0.152: P2.1 50.44,20.37 50.33,20.48 49.34,20.48 47.37,22.45 47.37,29.34 44.4,32.31 44.4,40.64 41.15,43.89 35.56,43.89 34.44,45.01 26.49,45.01 25.5,46 22.6,46 22.33,45.73 22.33,45.16 v1(22.66,44.83)
MX_0+: length 55.5
  TOP w0.152: T1.13 33.86,46.58 34.01,46.43 34.23,46.43 34.38,46.28 34.38,42.56 34.23,42.41 34.01,42.41 v1(33.68,42.74)
  BOTTOM w0.152: v1(33.68,42.74) 34.01,42.41 40.8,42.41 43.38,39.82 43.38,31.29 46.63,28.04 46.63,22.68 49.35,19.96 49.35,18.59 48.06,17.3 48.06,15.72 49,14.78 49,12.19 47.85,11.05 47.85,9.83 47.49,9.47 45.31,9.47 44.12,10.66 P2.11
MX_0-: length 47.7
  TOP w0.152: T1.14 35.26,46.58 35.11,46.43 34.89,46.43 34.74,46.28 34.74,42.41 34.38,42.05 34.01,42.05 v1(33.68,41.72)
  BOTTOM w0.152: P2.14 47.98,13.2 48.64,13.86 48.64,14.64 47.7,15.58 47.7,17.44 49,18.74 49,19.81 46.28,22.53 46.28,27.89 43.03,31.14 43.03,39.67 40.65,42.05 34.01,42.05 v1(33.68,41.72)
MX_1+: length 50.7
  TOP w0.152: T1.16 37.8,46.58 37.95,46.43 38.06,46.43 38.21,46.28 38.21,45.24 35.79,42.82 35.79,35.23 38.26,32.77 41.3,32.77 45.69,28.37 45.69,20.93 46.41,20.22 46.41,18.93 47.7,17.63 47.7,15.62 47.02,14.94 42.47,14.94 41.33,13.79 41.33,12.42 41.84,11.91 41.97,11.84 42.04,11.64 P2.9
MX_1-: length 50.4
  TOP w0.152: T1.17 39.07,46.58 38.92,46.43 38.72,46.43 38.57,46.28 38.57,45.1 36.14,42.67 36.14,35.38 38.4,33.12 41.45,33.12 46.05,28.52 46.05,21.08 46.76,20.37 46.76,19.08 48.06,17.78 48.06,15.47 47.17,14.58 42.62,14.58 41.68,13.64 41.68,12.57 42.05,12.2 42.13,12.16 42.34,12.23 P2.10
MX_2+: length 47.5
  TOP w0.152: P2.15 49.17,10.67 49.78,11.28 49.78,11.73 49,12.52 49,14.45 50.27,15.72 50.27,17.35 49,18.62 49,20.4 47.04,22.36 47.04,28.99 41.89,34.14 38.86,34.14 37.29,35.71 37.29,40.89 42.04,45.64 42.04,46.28 41.89,46.43 41.76,46.43 41.61,46.58 T1.19
MX_2-: length 47.1
  TOP w0.152: P2.16 50.44,12.45 50.16,12.17 49.86,12.17 49.35,12.67 49.35,14.31 50.62,15.58 50.62,17.5 49.35,18.77 49.35,20.55 47.4,22.5 47.4,29.13 42.04,34.49 39.01,34.49 37.64,35.86 37.64,40.74 42.4,45.49 42.4,46.25 42.57,46.43 42.73,46.43 42.88,46.58 T1.20
MX_3+: length 48.1
  TOP w0.152: T1.22 45.42,46.58 45.57,46.43 45.72,46.43 45.88,46.28 45.88,41.27 41.89,37.29 40.01,37.29 v1(39.65,37.64)
  BOTTOM w0.152: v1(39.65,37.64) 40.01,37.29 40.53,37.29 40.89,36.93 40.89,29.66 44.42,26.13 44.42,21.95 43.12,20.65 42.31,20.65 41.76,20.1 41.76,18.97 42.98,17.75 42.98,16.05 44.25,14.78 44.25,12.47 44.65,12.06 45.92,12.06 46.05,12.19 46.05,12.52 P2.12
MX_3-: length 48.9
  TOP w0.152: v1(39.65,36.63) 39.95,36.93 42.04,36.93 46.23,41.13 46.23,46.28 46.38,46.43 46.54,46.43 46.69,46.58 T1.23
  BOTTOM w0.152: v1(39.65,36.63) 39.95,36.93 40.39,36.93 40.54,36.78 40.54,29.51 44.07,25.98 44.07,22.1 42.98,21.01 42.16,21.01 41.4,20.24 41.4,18.82 42.62,17.6 42.62,15.9 43.89,14.63 43.89,12.32 44.5,11.71 46.48,11.71 46.63,11.56 P2.13
PHY_CPU_SGMII_N: length 129
  TOP w0.152: v1(40.71,174.45) 40.38,174.12 40.38,173.3 39.74,172.67 24.33,172.67 23.15,171.48 18.22,171.48 17.73,171 17.73,165.83 18.21,165.35 18.21,100.51 15.19,97.49 15.19,88.8 16.78,87.21 25.91,87.21 26.13,87.42 26.32,87.42 26.53,87.21 26.81,87.21 27.27,86.75 27.6,86.75 27.72,86.63 27.72,86.3 27.84,86.18 28.17,86.18 28.29,86.06 28.29,85.73 28.68,85.34 28.68,84.15 28.85,83.97 29.33,83.97 29.4,84.04 U10.1
  BOTTOM w0.152: v1(40.71,174.45) 40.38,174.12 40.38,173.8 40.6,173.58 J10.B30
PHY_CPU_SGMII_P: length 129
  TOP w0.152: U10.2 29.4,83.54 29.33,83.62 28.71,83.62 28.32,84 28.32,85.2 26.67,86.85 16.63,86.85 14.83,88.65 14.83,97.63 17.86,100.66 17.86,165.2 17.37,165.68 17.37,171.15 18.07,171.84 23,171.84 24.18,173.02 39.6,173.02 40.02,173.45 40.02,174.13 v1(39.69,174.45)
  BOTTOM w0.152: v1(39.69,174.45) 40.02,174.13 40.02,173.85 39.8,173.62 J10.B29
PHYAD_0: length 7.8
  TOP w0.203: v1(13.77,71.93) 13.73,71.89 U11.10 9.56,71.89 8.56,72.9 7.01,72.9 6.84,73.06 J5.2
PHYAD_1: length 5.9
  TOP w0.203: v1(12.12,71.4) 12.11,71.39 U11.11 9.33,71.39 8.92,71.81 7.01,71.81 6.84,71.97 J6.2
PHYAD_2: length 7
  TOP w0.203: J7.2 6.87,70.93 7.02,70.78 8.92,70.78 9.02,70.89 9.12,70.89 9.12,70.89 U11.12 13.08,70.89 v1(13.34,70.64)
PHYAD_3: length 6.2
  TOP w0.203: J8.2 6.87,69.87 7.01,69.72 8.76,69.72 9.43,70.39 U11.13 11.93,70.39 12.19,70.13 v1(12.19,70.03)
PHYAD_4: length 7.2
  TOP w0.203: J9.2 6.86,68.83 7.01,68.69 8.84,68.69 9.04,68.89 9.04,69.39 9.54,69.89 U11.14 11.41,69.89 11.84,69.47 v1(11.84,68.68)
RDAC: length 4.9
  TOP w0.203: v1(15.98,69.04) 15.51,68.57 U11.23 15.51,65.47 14.93,64.9 R64.2
RJ45_RXD: length 11.5
  TOP w0.203: L4.2 18.86,25.51 D2.2 18.88,20.69 22.08,17.49 P3.6
RJ45_TXD: length 8.5
  TOP w0.203: P3.3 30.18,23.8 D3.2 30.15,25.39 L6.2
RMIICRSDV: length 111.7
  TOP w0.203: R33.2 21.41,82.63 20.09,83.95 v1(18.87,83.95) ; v1(31.8,161.04) 31.83,161.07 31.83,167.46 30.2,169.09 v1(30.2,170.64)
  BOTTOM w0.203: J10.B17 v1(30.2,170.64) ; v1(31.8,161.04) 31.83,161 31.83,159.79 29.5,157.46 20.38,157.46 15.5,152.59 15.5,88.02 16.06,87.46 16.25,87.46 16.6,87.81 16.79,87.81 16.92,87.68 16.92,87.49 16.57,87.14 16.57,86.95 16.71,86.82 16.89,86.82 17.24,87.16 17.43,87.16 17.57,87.03 17.57,86.84 17.22,86.49 17.22,86.3 17.35,86.17 17.54,86.17 17.89,86.52 18.08,86.52 18.21,86.38 18.21,86.19 17.86,85.85 17.86,85.66 18,85.52 18.19,85.52 18.54,85.87 18.73,85.87 18.86,85.74 18.86,85.55 18.51,85.2 18.51,85.01 18.75,84.78 18.75,84.07 v1(18.87,83.95)
RMIICRSDV_R: length 3.2
  TOP w0.203: U11.49 20.11,79.31 20.58,79.78 v2(21.21,79.78) 21.41,79.98 R33.1
RMIIRXD0: length 113.1
  TOP w0.203: v5(32.54,162.36) 32.49,162.41 32.49,168.61 31,170.1 v1(31,170.96) ; R40.2 24.94,77.15 23.47,78.61 v1(21.87,78.61)
  BOTTOM w0.203: v5(32.54,162.36) 32.59,162.3 32.59,159.68 29.77,156.85 20.71,156.85 16.09,152.22 16.09,89.43 20.1,85.42 20.1,80.38 v1(21.87,78.61) ; J10.B18 v1(31,170.96)
RMIIRXD0_R: length 2.3
  TOP w0.203: U11.48 22.95,76.5 v1(23.32,76.86) 23.42,76.76 R40.1
RMIIRXD1: length 114.6
  TOP w0.203: v1(33.22,160.99) 33.26,161.02 33.26,163.16 33.1,163.32 33.1,168.85 31.8,170.15 v1(31.8,170.71) ; R43.2 25.24,75.71 25.66,76.13 25.66,77.29 23.68,79.27 v1(22.33,79.27)
  BOTTOM w0.203: v1(33.22,160.99) 33.22,159.38 30.09,156.25 20.99,156.25 16.68,151.93 16.68,89.72 20.76,85.63 20.76,80.84 v1(22.33,79.27) ; J10.B19 v1(31.8,170.71)
RMIIRXD1_R: length 2.3
  TOP w0.203: R43.1 23.46,75.71 v1(23.32,75.56) 22.99,75.89 U11.47
RMIIRXER: length 111.2
  TOP w0.203: v1(17.58,83.87) 18.26,83.19 20.02,83.19 20.24,82.97 R32.2 ; v1(29.4,170.73) 29.4,169.1 31.2,167.31 31.2,162.67 v5(31.17,162.64)
  BOTTOM w0.203: J10.B16 v1(29.4,170.73) ; v5(31.17,162.64) 31.2,162.61 31.2,160.02 29.23,158.05 20.09,158.05 14.91,152.88 14.91,86.53 15.21,86.24 15.4,86.24 15.81,86.65 16,86.65 16.13,86.52 16.13,86.33 15.72,85.92 15.72,85.73 15.85,85.59 16.04,85.59 16.45,86.01 16.64,86.01 16.78,85.87 16.78,85.68 16.37,85.27 16.37,85.08 16.5,84.95 16.69,84.95 17.1,85.36 17.29,85.36 17.42,85.22 17.42,85.04 17.01,84.62 17.01,84.43 v1(17.58,83.87)
RMIIRXER_R: length 3.3
  TOP w0.203: U11.51 19.01,79.76 19.21,79.96 v2(19.91,79.96) 20.24,80.29 R32.1
RMIITXD0: length 103.3
  TOP w0.203: U11.57 16.01,79.6 15.53,80.08 v1(15.53,81.08) ; v1(29.19,159.86) 29.19,159.86 29.19,166.16 v1(29.06,166.29)
  BOTTOM w0.203: v1(15.53,81.08) 15.53,82.51 13.22,84.82 13.22,153.93 19.15,159.86 v1(29.19,159.86) ; v1(29.06,166.29) 29.4,166.64 J10.A16
RMIITXD1: length 104.3
  TOP w0.203: v5(29.93,165.58) 29.93,160.73 v1(29.89,160.69) ; U11.58 15.51,79.31 14.94,79.88 v1(14.94,82.01)
  BOTTOM w0.203: v1(29.89,160.69) 29.69,160.48 18.71,160.48 12.63,154.39 12.63,84.32 v1(14.94,82.01) ; J10.A17 30.2,166.34 29.93,166.07 v5(29.93,165.58)
RMIITXEN: length 102
  TOP w0.203: v5(28.5,165.48) 28.45,165.43 28.45,159.33 v1(28.47,159.31) ; U11.56 16.51,79.75 16.28,79.98 v1(16.28,80.57)
  BOTTOM w0.203: J10.A14 27.8,166.67 28.5,165.97 v5(28.5,165.48) ; v1(16.28,80.57) 16.28,82.88 13.81,85.35 13.81,153.35 19.65,159.19 28.34,159.19 v1(28.47,159.31)
ROUT2: length 2.2
  TOP w0.203: U13.18 12.83,55.89 v1(12.83,57.23) R72.2
RXD: length 23.7
  TOP w0.203: R75.1 16.52,29.75 v1(16.5,29.77) ; U13.5 8.92,45.26 v1(8.96,45.22)
  BOTTOM w0.203: v1(8.96,45.22) 16.52,37.66 16.52,29.79 v1(16.5,29.77)
TESTEN_5221: length 3.9
  TOP w0.203: R58.2 v2(8.41,68.07) 9.04,68.07 9.45,68.48 9.45,69.19 9.65,69.39 U11.15
TS_BITCLK_OUT: length 182.1
  TOP w0.203: P4.2 8.42,6.27 8.42,11.19 11.14,13.91 D5.1 12.13,14.4 12.54,14.81 12.54,18.81 3.23,28.12 3.23,94.75 13.58,105.09 13.58,168.02 v1(13.41,168.19)
  BOTTOM w0.203: J10.B1 14.38,172.47 13.57,171.66 13.57,168.35 v1(13.41,168.19)
TXD: length 30.4
  TOP w0.203: R76.1 27.83,37.21 23.74,41.3 18.24,41.3 v2(14.63,44.91) 12.17,47.37 U13.10
UART1_3243_RXD: length 124.4
  TOP w0.203: v1(20.95,165.17) 20.9,165.21 20.9,167.34 v1(23.11,169.54) ; R72.1 12.83,59.56 v1(11.73,60.66)
  BOTTOM w0.203: J10.A8 23,169.43 v1(23.11,169.54) ; v1(11.73,60.66) 11.73,60.68 5.61,66.8 5.61,78.36 9.57,82.31 9.57,156.7 17.63,164.76 20.55,164.76 v1(20.95,165.17)
UART1_3243_TXD: length 135.5
  TOP w0.203: v1(20.92,164.34) 21.72,165.14 21.72,167.31 23.83,169.42 v1(23.83,169.9) ; U13.13 14.12,50.2 13.34,50.98 v1(13.26,50.98)
  BOTTOM w0.203: v1(20.92,164.34) 17.8,164.34 10,156.54 10,82.01 6.81,78.82 6.81,67.31 13.49,60.63 13.49,51.21 v1(13.26,50.98) ; J10.A9 23.8,169.88 v1(23.83,169.9)
USB1_DM: length 88.3
  TOP w0.14: v1(8,106.02) 7.57,105.58 N2.2 ; v1(26.26,35.47) 25.88,35.09 25.88,34.85 26.21,34.52 U14.1 N6.1
  BOTTOM w0.14: v1(26.26,35.47) 25.88,35.85 25.88,36.47 22.53,39.83 17.6,39.83 3.65,53.77 3.65,99.36 7.67,103.39 7.67,105.69 v1(8,106.02)
USB1_DM_C: length 33.8
  TOP w0.14: v1(26.24,30.26) 25.91,30.59 25.91,30.96 26.21,31.26 U14.2 N6.2 ; v1(26.04,27.74) 25.65,27.36 25.37,27.36 25.15,27.58 25.15,27.99 25.01,28.13 D1.3
  BOTTOM w0.14: v1(26.24,30.26) 25.86,30.65 25.86,31.21 26.01,31.37 26.69,31.37 27.1,30.96 27.1,27.66 26.79,27.36 26.42,27.36 v1(26.04,27.74) 25.65,27.36 24.35,27.36 23.88,26.88 23.88,23.01 25.02,21.87 25.02,19.2 26.16,18.06 26.16,14.71 24.37,12.92 24.37,10.92 P3.10
USB1_DP: length 88.2
  TOP w0.14: N1.2 7.61,106.52 v1(7.11,106.02) ; N5.1 U14.4 25.35,34.52 25.63,34.8 25.63,35.09 v1(25.25,35.47)
  BOTTOM w0.14: v1(25.25,35.47) 25.63,35.85 25.63,36.37 22.42,39.57 17.49,39.57 3.39,53.67 3.39,99.47 7.42,103.49 7.42,105.71 v1(7.11,106.02)
USB1_DP_C: length 34.8
  TOP w0.14: N5.2 U14.3 25.35,31.26 25.65,30.96 25.65,30.7 v1(25.22,30.26) ; D1.1 24.96,26.23 25.15,26.42 25.15,26.94 25.31,27.1 25.65,27.1 v1(26.04,26.72)
  BOTTOM w0.14: v1(25.22,30.26) 25.6,30.65 25.6,31.32 25.91,31.62 26.8,31.62 27.36,31.06 27.36,27.56 26.9,27.1 26.42,27.1 v1(26.04,26.72) 25.65,27.1 24.46,27.1 24.13,26.77 24.13,23.11 25.27,21.97 25.27,19.3 26.42,18.16 26.42,14.61 24.63,12.82 24.63,10.92 P3.11
USB1_DRVVBUS: length 24.8
  TOP w0.203: U1.4 8.92,169.14 v1(8.98,169.2)
  BOTTOM w0.203: v1(8.98,169.2) 9,169.22 R81.2 9,170.8 v2(13.14,174.94) 16.32,178.12 21.87,178.12 23,176.99 J10.B8
USB1_GND_C: length 17.4
  TOP w0.762: L5.2 33.2,21.39 30.35,18.55 30.35,12.4 P3.12
USB1_OC#: length 26.2
  TOP w0.203: v1(11.12,171.58) 11.34,171.35 11.34,169.67 9.73,168.05 9.73,167.21 8.92,166.4 U1.3
  BOTTOM w0.203: J10.B7 22.2,173.81 22.53,174.14 22.53,176.77 21.61,177.69 16.81,177.69 11.12,172 v1(11.12,171.58)
USB1_VBUS: length 135.8
  TOP w0.762: L3.2 9.21,40.8 v4(9.1,40.91) ; v4(5.44,114.88) 5.44,114.95 8.36,117.88 8.36,154.47 9.32,155.43 9.32,162.2 6.99,164.54 U1.1
  BOTTOM w0.762: v4(9.1,40.91) 6.54,43.48 6.52,43.48 2.16,47.84 2.16,111.68 5.37,114.88 v4(5.44,114.88)
USB1_VBUS_C: length 44.2
  TOP w0.356: C68.2 15.04,31.01 15.24,30.81
  TOP w0.762: L3.1 14.94,40.79 14.94,35.6 C67.1 15.24,30.81 ; 15.24,30.81 15.24,20.93 17.86,18.31 17.86,13.19 P3.9 ; 15.24,30.81 15.37,30.94 19.05,30.94 20.24,29.75 20.24,27.71 20.77,27.18 D1.5
USB_CAB_DN: length 3.4
  TOP w0.14: N2.3 6.68,105.18 6.24,105.62 4.81,105.62 JP1.2
USB_CAB_DP: length 3.9
  TOP w0.14: 3.94,106.74 4.81,105.87 6.2,105.87 6.72,106.39 N1.3
USB_MGT_DN: length 84.2
  TOP w0.14: v1(19.86,176.57) 19.47,176.18 19.47,175.76 19.13,175.43 15.36,175.43 12.63,172.71 12.63,169.1 11.19,167.66 11.19,106.65 10.39,105.85 9.55,105.85 9.41,105.71 9.41,105.17 9.27,105.03 N2.1
  BOTTOM w0.14: v1(19.86,176.57) 19.47,176.18 19.47,175.72 20.3,174.89 20.3,173.87 20.6,173.57 J10.B5
USB_MGT_DP: length 83.7
  TOP w0.14: v1(18.84,176.57) 19.21,176.2 19.21,175.87 19.03,175.68 15.25,175.68 12.38,172.81 12.38,169.21 10.94,167.77 10.94,106.76 10.29,106.1 9.55,106.1 9.41,106.24 9.41,106.78 9.27,106.92 N1.1
  BOTTOM w0.14: v1(18.84,176.57) 19.21,176.2 19.21,175.62 20.05,174.78 20.05,173.91 19.8,173.66 J10.B4
VN: length 2.3
  TOP w0.203: C65.2 7.87,47.07 8.06,47.25 ; 8.06,47.25 v1(8.09,47.25) ; 8.06,47.25 7.62,47.7 U13.3
VP: length 3.3
  TOP w0.203: R69.2 C61.2 6.86,57.51 v1(7.09,57.28) 6.97,57.16 U13.27
N16967289: length 4.2
  TOP w0.203: R56.2 23.67,69.34 23.12,69.89 U11.35 21.28,69.89 20.7,69.32 v1(20.7,68.96)
N16969721: length 4
  TOP w0.203: v1(20.23,63.11) R66.2 20.33,63.69 C54.1 ; v1(18.72,63.12) 18.68,63.15 R67.2
  BOTTOM w0.203: v1(18.72,63.12) 20.22,63.12 v1(20.23,63.11)
N16969742: length 4.9
  TOP w0.203: R68.2 v1(17.48,62.89) ; v1(15.19,62.84) C59.1 15.99,62.85 R65.2
  BOTTOM w0.203: v1(15.19,62.84) 17.42,62.84 v1(17.48,62.89)
N16975167: length 5.4
  TOP w0.254: U11.2 9.53,75.89 9.42,76 8.1,76 C33.1 C32.1 C30.1
  TOP w0.305: C30.1 v2(7.99,78.73)
N16979054: length 4.5
  TOP w0.254: C27.1 C26.1 C25.1 17.01,80.71 v1(17.01,79.76) U11.55
N16981835: length 2.5
  TOP w0.203: U11.17 12.4,64.95 TP3.1
N16997753: length 3.5
  TOP w0.203: v1(20.75,70.23) 20.91,70.39 U11.36 24.13,70.39 R55.1
N17348775: length 1.5
  TOP w0.203: R7.1 v1(40.51,93.64) 41.38,93.64 U4.6
N17369682: length 3.3
  TOP w0.203: L4.1 17.27,27.93 R75.2 17.26,29.21 C70.1 17.25,30.06 v1(17.3,30.1)
N17369686: length 45.8
  TOP w0.203: L6.1 28.57,27.8 R76.2 28.56,29.06 C71.1 28.55,30.5 v1(28.52,30.53) ; R69.1 v1(7.87,59.56)
  BOTTOM w0.203: v1(28.52,30.53) 28.56,30.57 28.56,36.69 24.1,41.15 18.13,41.15 9.53,49.75 9.53,55.73 7.87,57.38 v1(7.87,59.56)
N17369693: length 8.1
  TOP w0.203: C60.1 5.84,59.82 6.1,60.07 v2(6.1,60.12) 6.17,60.2 8.13,60.2 8.51,59.82 8.51,57.3 8.92,56.9 U13.24
N17377991: length 2.8
  TOP w0.356: JP1.1 6.72,102.74 C15.1
N17393087: length 14.7
  TOP w0.356: T2.7 22.16,58.89 v1(22.15,58.9) ; T2.2 28.48,57.71 28.48,58.9 v1(28.47,58.9) ; L2.2 19.3,58.78 v1(19.33,58.75)
  BOTTOM w0.356: C131.1 20.06,58.02 v1(19.33,58.75) ; C131.1 22.2,58.05 C130.1 28.48,58.9 v1(28.47,58.9) ; C131.1 22.16,58.02 22.16,58.89 v1(22.15,58.9)
N17393095: length 10.9
  TOP w0.508: C62.1 17.67,49.7 v4(19.47,49.7)
  BOTTOM w0.508: R84.2 22.13,49.7 R85.2 v4(19.47,49.7)
N17393120: length 2.6
  TOP w0.508: T2.15 28.51,47.29 v3(28.49,47.27)
  BOTTOM w0.508: R84.1 28.53,47.31 v3(28.49,47.27)
N17393125: length 2.6
  TOP w0.508: T2.10 v3(22.16,47.23)
  BOTTOM w0.508: R85.1 22.16,48.36 v3(22.16,47.23)
N17394746: length 13
  TOP w0.203: R74.2 41.53,26.77 41.73,26.57 42.9,26.57 44.58,24.89 44.58,20.22 P2.5 P2.4
N17394754: length 14.1
  TOP w0.203: R73.2 40.13,26.62 40.73,26.02 42.71,26.02 44.09,24.64 44.09,20.7 P2.7 P2.8
N17394762: length 4.6
  TOP w0.152: R74.1 v2(42.74,28.61)
  TOP w0.203: R74.1 R73.1 40.13,30.25 C69.2
N17500188: length 8.1
  TOP w0.203: U6.13 v1(18.95,93.71) ; U6.3 20.22,91.35 20.02,91.56 19.09,91.56 v1(18.95,91.42) U6.2
  BOTTOM w0.203: v1(18.95,91.42) v1(18.95,93.71)
N17503699: length 9.9
  TOP w0.203: U6.11 21.49,94.78 21.89,94.39 23.97,94.39 v1(24.04,94.46) 24.04,94.88 24.05,94.89 24.05,96.03 U6.9 ; v1(24.26,91.77) 24.03,91.55 U6.6
  BOTTOM w0.203: v1(24.04,94.46) 24.04,91.99 v1(24.26,91.77)
N17554281: length 17
  TOP w0.508: U3.1 42.19,104.65 40.14,104.65 R2.1 40.11,103.71 v4(40.16,103.66) ; R3.2 52.37,103.01 v4(52.04,102.67)
  BOTTOM w0.508: v4(52.04,102.67) 52.02,102.69 41.12,102.69 v4(40.16,103.66)
N17554333: length 4.6
  TOP w0.305: R1.1 24.07,105.47 v2(23.88,105.28)
  TOP w0.508: U2.1 27.37,105.47 R1.1 R4.2
N17555126: length 6.3
  TOP w0.203: X1.4 34.02,134.53 v4(33.27,133.78) 32.69,133.2 J1.1
N17555132: length 5.4
  TOP w0.203: X2.3 33.67,126.24 v4(33.16,126.76) 32.69,127.23 J1.3
N17584781: length 5.7
  TOP w0.203: J3.2 8.36,86.44 8.53,86.61 8.53,88.19 7.95,88.77 U7.2 v1(7.95,91.39)
N17584783: length 6
  TOP w0.203: v1(6.2,91.31) 6.55,90.96 U7.1 6.55,88.75 7.19,88.11 7.19,86.69 6.93,86.44 J2.2
N17584789: length 4.6
  TOP w0.203: J4.2 9.73,86.44 10.08,86.79 v2(10.08,87.55) 10.08,88.34 9.22,89.2 U7.3
N17714670: length 4.9
  TOP w0.305: C66.1 v2(48.59,40.89)
  TOP w0.762: C66.1 50,40.83 A4.6
N17714694: length 5
  TOP w0.305: C3.1 v2(50.83,165.79)
  TOP w0.762: A2.6 53,164.91 C3.1
N17714718: length 4.6
  TOP w0.305: v2(9.17,29.24) 9.12,29.18 C73.1
  TOP w0.762: C73.1 7.95,32.5 A3.7
N17714742: length 4.9
  TOP w0.305: C5.1 v2(6.96,154.18)
  TOP w0.762: A1.7 5,154.97 C5.1
N51850856: length 4.3
  TOP w0.203: 46.27,83.12 46.28,83.14 U9.4 ; 46.27,83.12 R29.2 ; 46.27,83.12 R27.1 v2(48.68,83.12)
N51850909: length 5.1
  TOP w0.203: v1(31.27,92) 31.29,92 31.85,91.44 U5.4 33.13,90.54 33.4,90.81 R8.2 34.6,91.27 R9.1
N51852031: length 2.4
  TOP w0.203: R57.2 47.35,69.04 v2(47.22,68.91)
  TOP w0.305: R57.2 48.04,69.22
  TOP w0.508: 48.04,69.22 L1.1
N51852050: length 4.5
  TOP w0.203: X3.3 47.08,76.34 v1(45.49,76.34) R41.1
N51852054: length 10
  TOP w0.203: v2(50.5,70.1) 50.29,70.31 49.49,70.31
  TOP w0.356: 49.58,73.74 49.4,73.56 C35.1 ; C34.1 49.43,74.61 49.58,74.75
  TOP w0.508: L1.2 49.49,70.31 49.57,70.39 ; 49.58,72.11 49.55,72.08 C36.1
  TOP w0.762: 49.57,70.39 49.58,70.4 X3.4 X3.1
N51852604: length 3.7
  TOP w0.203: N3.1 27.55,83.1 C23.2 27.61,83.04 28.36,83.04 28.4,83.01 v2(28.52,83.01) 28.56,83.04 U10.3
N51852612: length 4.1
  TOP w0.203: N4.1 28.3,78.57 ; 28.3,78.57 C31.2 ; 28.3,78.57 28.33,78.54 U10.12
  TOP w0.305: v2(28.04,76.5) 28.3,76.77 C31.2
N57500449: length 22.1
  TOP w0.203: P2.22 36.96,6.6 36.17,7.39 36.17,22.25 34.91,23.51 R80.2
N172653170: length 2.5
  TOP w0.203: U11.61 14.01,80.91 TP2.1
N172654950: length 4.2
  TOP w0.203: TP1.1 13.16,82.13 13.16,80.04 13.51,79.69 U11.62

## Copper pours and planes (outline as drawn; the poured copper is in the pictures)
3.3V_OCXO on TOP: 40.54,111.75 45.29,106.99 45.29,104.48 44.41,103.59 41.21,103.59 40.82,103.2 40.82,101.91 41.4,101.33 44.09,101.33 45.48,99.95 50.32,99.95 51.49,101.12 51.49,108.61 46.55,113.54 46.55,135.09 44.92,136.73 40.59,136.73 39.93,136.07 39.93,132.16 40.44,131.65 42.67,131.65 43.22,131.1 43.22,127.98 42.75,127.51 41.37,127.51 40.54,126.68
7V_OCXO on TOP: 36.33,105.99 30.23,105.99 28.32,104.09 26.42,104.09 26.16,103.84 26.16,102.44 26.41,102.19 28.76,102.19 31.94,99.01 43.11,99.01 43.67,99.57 43.67,100.79 43.39,101.07 41.25,101.07
GND on TOP: -1.7,183.01 -1.7,-2.79 59.16,-2.79 59.16,183.01 ; 36 cut-outs
GND on BOTTOM: -1.7,183.01 -1.7,-2.79 59.16,-2.79 59.16,183.01 ; 16 cut-outs
GND on L2_GND: -1.7,183.01 -1.7,-2.79 59.16,-2.79 59.16,183.01 ; 4 cut-outs
GND on L3_VCC: 56.79,97.6 22.04,97.6 19.94,99.7 19.94,152.27 32.16,164.49 32.16,170.46 32.74,171.04 35.84,171.04 37.21,172.42 37.21,176.15 40.13,179.07 56.52,179.07 58.04,177.55 58.04,98.85 ; 1 cut-out
VCC3P3 on L3_VCC: 27.53,93.26 37.77,93.26 38.95,92.08 40.17,92.08 41.74,93.65 44.4,93.65 45.7,92.35 47.48,92.35 51.82,88.01 51.82,66.98 50.9,66.06 47.01,66.06 46.33,66.74 46.33,88.04 44.46,89.91 30.02,89.91 30,89.89 28.37,89.89 28.17,89.69 28.17,88.54 27.98,88.35 26.23,88.35 25.98,88.6 25.98,91.71
VDD1P2 on L3_VCC: 39.75,79.12 40.48,79.12 40.68,79.32 40.68,84.85 40.31,85.22 32.75,85.22 31.15,86.81 31.15,87.65 31.75,88.25 31.75,89.37 31.46,89.66 28.5,89.66 28.39,89.55 28.39,88.36 28.03,87.99 26.98,87.99 26.42,87.43 26.42,78.61 26.8,78.23 38.86,78.23
VDD2P5 on L3_VCC: 23.76,97.03 54.49,97.03 56.01,95.52 56.01,59.9 27.43,59.9 27.43,70.99 21.74,76.68 21.74,95.02
VDD12P0 on TOP: 28.43,101.89 25.74,101.89 25.81,101.83 25.1,101.83 24.99,101.73 24.99,99.04 25.37,98.65 28.52,98.65 28.88,99.01 28.88,101.44
BIAS3V3 on L3_VCC: 51.56,25.96 51.56,28.05 50.04,29.57 20.72,29.57 19.94,30.35 19.94,55.5 26.92,62.48 26.92,70.74 21.03,76.63 21.03,95.3 18.92,97.41 18.92,153.54 30.58,165.2 30.58,171.53 31.93,172.87 34.37,172.87 35.33,173.84 35.33,176.31 33.72,177.92 2.79,177.92 2.03,177.16 2.03,24.77 5.08,21.72 47.32,21.72 ; 2 cut-outs
MNG_PHY_VDDA on L3_VCC: 32,75.18 37.21,75.18 39.19,77.17 40.03,77.17 40.56,76.63 40.56,76.4 38.07,73.91 32,73.91
N17714670 on TOP (solid shape): outline of 222 points within 46.95,31.95 53.05,38.05
N17714670 on BOTTOM (solid shape): outline of 222 points within 46.95,31.95 53.05,38.05
N17714694 on TOP (solid shape): outline of 222 points within 49.95,156.95 56.05,163.05
N17714694 on BOTTOM (solid shape): outline of 222 points within 49.95,156.95 56.05,163.05
N17714718 on TOP (solid shape): outline of 222 points within 4.95,31.95 11.05,38.05
N17714718 on BOTTOM (solid shape): outline of 222 points within 4.95,31.95 11.05,38.05
N17714742 on TOP (solid shape): outline of 222 points within 1.95,156.95 8.05,163.05
N17714742 on BOTTOM (solid shape): outline of 222 points within 1.95,156.95 8.05,163.05

Small or netless copper shapes (teardrops, artwork), in the pictures only: 289 on TOP, 200 on BOTTOM

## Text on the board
Ref Des/Silkscreen Top: AESIHTMG
User.23: FIGURE | SIZE | 10.0 | 15.0 | 20.0 | 35.0 | 40.0 | 55.0 | 75.0 | 90.0 | 31.0 | 47.0 | 80.0 | 126.0 | 85.0x70.0 | DRILL CHART: TOP to BOTTOM | ALL UNITS ARE IN MILS | TOLERANCE | +3.0/-3.0 | +2.0/-2.0 | PLATED | NON-PLATED | QTY | 802 | 110 | 78 | 37 | 4 | 2 | 6 | 1
